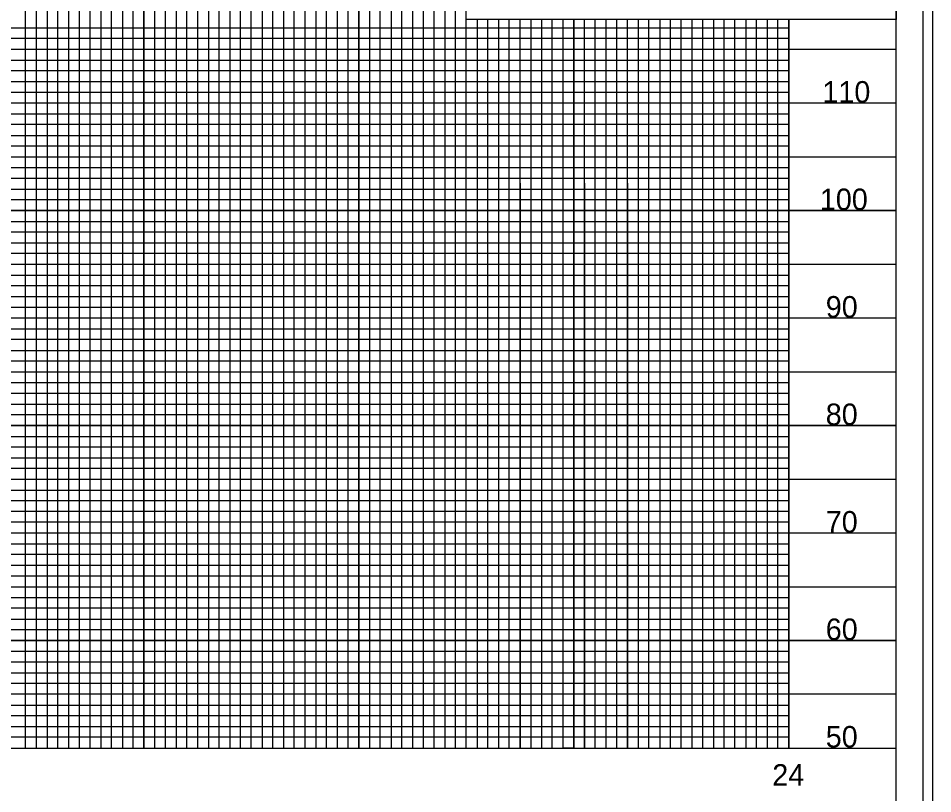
# Model space of a CAD drawing. Extents: x 2367101 to 2368930, y 803279 to 808979.
# Drawn here: x 2368359.6 to 2368785, y 803832.7 to 804193.5 of the extents above; entities that cross this region are included whole.
import ezdxf

# ---------------------------------------------------------------- set-up
doc = ezdxf.new("R2010")
doc.units = 0
for name, color, linetype in [('Old_Level_11', 7, 'Continuous'), ('Old_Level_12', 7, 'Continuous'), ('Old_Level_13', 7, 'Continuous'), ('Old_Level_17', 7, 'Continuous'), ('Old_Level_19', 7, 'Continuous'), ('Old_Level_4', 7, 'Continuous'), ('Old_Level_6', 7, 'Continuous'), ('Old_Level_63', 7, 'Continuous'), ('Old_Level_8', 7, 'Continuous'), ('Old_Level_9', 7, 'Continuous'), ('Plan Sheet CELL', 7, 'Continuous')]:
    doc.layers.add(name, color=color, linetype=linetype)

msp = doc.modelspace()

# ---------------------------------------------------------------- linework, layer by layer
at = {"layer": 'Old_Level_11'}
for points in [[(2368317.97, 803853.98), (2368367.97, 803853.98), (2368367.97, 804353.98), (2368417.97, 804353.98), (2368417.97, 803853.98), (2368467.97, 803853.98), (2368467.97, 804353.98), (2368517.97, 804353.98), (2368517.97, 803853.98), (2368567.97, 803853.98), (2368567.97, 804353.98), (2368594.27, 804353.98)], [(2368717.97, 804192.93), (2368717.97, 803853.98), (2368767.97, 803853.98), (2368767.97, 804203.98)], [(2368617.97, 804192.93), (2368617.97, 803853.98), (2368667.97, 803853.98), (2368667.97, 803853.98), (2368667.97, 804192.93)], [(2368767.97, 804153.98), (2367267.97, 804153.98), (2367267.97, 804103.98), (2368767.97, 804103.98)], [(2368767.97, 804053.98), (2367267.97, 804053.98), (2367267.97, 804003.98), (2368767.97, 804003.98)], [(2368767.97, 803953.98), (2367267.97, 803953.98), (2367267.97, 803953.98), (2367267.97, 803903.98), (2368767.97, 803903.98)]]:
    msp.add_lwpolyline(points, dxfattribs=at)
at = {"layer": 'Old_Level_12'}
for points in [[(2368342.97, 803853.98), (2368392.97, 803853.98), (2368392.97, 804353.98), (2368442.97, 804353.98), (2368442.97, 803853.98), (2368492.97, 803853.98), (2368492.97, 804353.98), (2368542.97, 804353.98), (2368542.97, 803853.98), (2368592.97, 803853.98), (2368592.97, 804192.93)], [(2368592.97, 804116.78), (2368592.97, 803853.98), (2368642.97, 803853.98), (2368642.97, 804192.93)], [(2368642.97, 804116.78), (2368642.97, 803853.98), (2368692.97, 803853.98), (2368692.97, 804192.93)], [(2368767.97, 804178.98), (2367267.97, 804178.98), (2367267.97, 804128.98), (2368592.97, 804128.98)], [(2368592.97, 804128.98), (2368767.97, 804128.98)], [(2368767.97, 804078.98), (2367267.97, 804078.98), (2367267.97, 804028.98), (2368767.97, 804028.98)], [(2368767.97, 803978.98), (2367267.97, 803978.98), (2367267.97, 803928.98), (2368767.97, 803928.98)], [(2368767.97, 803878.98), (2367267.97, 803878.98)]]:
    msp.add_lwpolyline(points, dxfattribs=at)
at = {"layer": 'Old_Level_13'}
for p, q in [((2368367.97, 803853.98), (2368367.97, 804353.98)), ((2368417.97, 803853.98), (2368417.97, 804353.98)), ((2368467.97, 803853.98), (2368467.97, 804353.98)), ((2368517.97, 803853.98), (2368517.97, 804353.98)), ((2368567.97, 803853.98), (2368567.97, 804216.43)), ((2368617.97, 803853.98), (2368617.97, 804192.93)), ((2368667.97, 803853.98), (2368667.97, 804192.93)), ((2368717.97, 803853.98), (2368717.97, 804192.93)), ((2368767.97, 804153.98), (2367267.97, 804153.98)), ((2368767.97, 804103.98), (2367267.97, 804103.98)), ((2368767.97, 804053.98), (2367267.97, 804053.98)), ((2368767.97, 804003.98), (2367267.97, 804003.98)), ((2368767.97, 803953.98), (2367267.97, 803953.98)), ((2368767.97, 803903.98), (2367267.97, 803903.98))]:
    msp.add_line(p, q, dxfattribs=at)
at = {"layer": 'Old_Level_4'}
msp.add_lwpolyline([(2367113.97, 803301.43), (2368780.47, 803301.43), (2368780.47, 804356.53), (2367113.97, 804356.53)], close=True, dxfattribs=at)
at = {"layer": 'Old_Level_6'}
msp.add_lwpolyline([(2367100.97, 803278.98), (2368784.97, 803278.98), (2368784.97, 804378.98), (2367100.97, 804378.98)], close=True, dxfattribs=at)
at = {"layer": 'Old_Level_63'}
msp.add_lwpolyline([(2367317.97, 804192.93), (2367317.97, 803853.98), (2368717.97, 803853.98), (2368717.97, 804192.93)], dxfattribs=at)
at = {"layer": 'Old_Level_8'}
for p, q in [((2367317.97, 804188.98), (2368717.97, 804188.98)), ((2368717.97, 804168.98), (2367317.97, 804168.98)), ((2367317.97, 804163.98), (2368717.97, 804163.98)), ((2368717.97, 804143.98), (2367317.97, 804143.98)), ((2367317.97, 804138.98), (2368717.97, 804138.98)), ((2368717.97, 804118.98), (2367317.97, 804118.98)), ((2367317.97, 804113.98), (2368717.97, 804113.98)), ((2368717.97, 804108.98), (2367317.97, 804108.98)), ((2367317.97, 804098.98), (2368717.97, 804098.98)), ((2368717.97, 804093.98), (2367317.97, 804093.98)), ((2367317.97, 804088.98), (2368717.97, 804088.98)), ((2368717.97, 804083.98), (2367317.97, 804083.98)), ((2367317.97, 804073.98), (2368717.97, 804073.98)), ((2368717.97, 804068.98), (2367317.97, 804068.98)), ((2367317.97, 804063.98), (2368717.97, 804063.98)), ((2368717.97, 804058.98), (2367317.97, 804058.98)), ((2367317.97, 804048.98), (2368717.97, 804048.98)), ((2368717.97, 804043.98), (2367317.97, 804043.98)), ((2367317.97, 804038.98), (2368717.97, 804038.98)), ((2368717.97, 804033.98), (2367317.97, 804033.98)), ((2367317.97, 804023.98), (2368717.97, 804023.98)), ((2368717.97, 804018.98), (2367317.97, 804018.98)), ((2367317.97, 804013.98), (2368717.97, 804013.98)), ((2368717.97, 804008.98), (2367317.97, 804008.98)), ((2367317.97, 803998.98), (2368717.97, 803998.98)), ((2368717.97, 803993.98), (2367317.97, 803993.98)), ((2367317.97, 803988.98), (2368717.97, 803988.98)), ((2368717.97, 803983.98), (2367317.97, 803983.98)), ((2367317.97, 803973.98), (2368717.97, 803973.98)), ((2368717.97, 803968.98), (2367317.97, 803968.98)), ((2368717.97, 803963.98), (2367317.97, 803963.98)), ((2368717.97, 803958.98), (2367317.97, 803958.98)), ((2367317.97, 803948.98), (2368717.97, 803948.98)), ((2368717.97, 803943.98), (2367317.97, 803943.98)), ((2367317.97, 803938.98), (2368717.97, 803938.98)), ((2368717.97, 803933.98), (2367317.97, 803933.98)), ((2367317.97, 803923.98), (2368717.97, 803923.98)), ((2368717.97, 803918.98), (2367317.97, 803918.98)), ((2367317.97, 803913.98), (2368717.97, 803913.98)), ((2368717.97, 803908.98), (2367317.97, 803908.98)), ((2367317.97, 803898.98), (2368717.97, 803898.98)), ((2368717.97, 803893.98), (2367317.97, 803893.98)), ((2367317.97, 803888.98), (2368717.97, 803888.98)), ((2368717.97, 803883.98), (2367317.97, 803883.98)), ((2367317.97, 803873.98), (2368717.97, 803873.98)), ((2368717.97, 803868.98), (2367317.97, 803868.98)), ((2367317.97, 803863.98), (2368717.97, 803863.98))]:
    msp.add_line(p, q, dxfattribs=at)
for points in [[(2368357.97, 803853.98), (2368362.97, 803853.98), (2368362.97, 804353.98)], [(2368372.97, 804353.98), (2368372.97, 803853.98), (2368377.97, 803853.98), (2368377.97, 804353.98)], [(2368382.97, 804353.98), (2368382.97, 803853.98), (2368387.97, 803853.98), (2368387.97, 804353.98)], [(2368397.97, 804353.98), (2368397.97, 803853.98), (2368402.97, 803853.98), (2368402.97, 804353.98)], [(2368407.97, 804353.98), (2368407.97, 803853.98), (2368412.97, 803853.98), (2368412.97, 804353.98)], [(2368422.97, 804353.98), (2368422.97, 803853.98), (2368427.97, 803853.98), (2368427.97, 804353.98)], [(2368432.97, 804353.98), (2368432.97, 803853.98), (2368437.97, 803853.98), (2368437.97, 804353.98)], [(2368447.97, 804353.98), (2368447.97, 803853.98), (2368452.97, 803853.98), (2368452.97, 804353.98)], [(2368457.97, 804353.98), (2368457.97, 803853.98)], [(2368457.97, 803853.98), (2368462.97, 803853.98), (2368462.97, 804353.98)], [(2368472.97, 804353.98), (2368472.97, 803853.98), (2368477.97, 803853.98), (2368477.97, 804353.98)], [(2368482.97, 804353.98), (2368482.97, 803853.98), (2368487.97, 803853.98), (2368487.97, 804353.98)], [(2368497.97, 804353.98), (2368497.97, 803853.98), (2368502.97, 803853.98), (2368502.97, 804353.98)], [(2368507.97, 804353.98), (2368507.97, 803853.98), (2368512.97, 803853.98), (2368512.97, 804353.98)], [(2368522.97, 804353.98), (2368522.97, 803853.98), (2368527.97, 803853.98), (2368527.97, 804353.98)], [(2368532.97, 804353.98), (2368532.97, 803853.98), (2368537.97, 803853.98), (2368537.97, 804353.98)], [(2368547.97, 804353.98), (2368547.97, 803853.98), (2368552.97, 803853.98), (2368552.97, 804353.98)], [(2368557.97, 804353.98), (2368557.97, 803853.98), (2368562.97, 803853.98), (2368562.97, 804353.98)], [(2368572.97, 804192.93), (2368572.97, 803853.98), (2368577.97, 803853.98), (2368577.97, 804192.93)], [(2368582.97, 804192.93), (2368582.97, 803853.98), (2368587.97, 803853.98), (2368587.97, 804192.93)], [(2368597.97, 804192.93), (2368597.97, 803853.98), (2368597.97, 803853.98), (2368602.97, 803853.98), (2368607.97, 803853.98), (2368607.97, 804192.93)], [(2368602.97, 804192.93), (2368602.97, 803853.98)], [(2368612.97, 804192.93), (2368612.87, 803854.03), (2368617.87, 803854.03), (2368622.97, 803853.98), (2368622.97, 804192.93)], [(2368622.97, 804116.78), (2368622.97, 803853.98), (2368627.97, 803853.98), (2368627.97, 804192.93)], [(2368632.97, 804192.93), (2368632.97, 803853.98), (2368637.97, 803853.98), (2368637.97, 804192.93)], [(2368647.97, 804192.93), (2368647.97, 803853.98), (2368652.97, 803853.98), (2368652.97, 804192.93)], [(2368657.97, 804192.93), (2368657.97, 803853.98), (2368662.97, 803853.98), (2368662.97, 804192.93)], [(2368672.97, 804192.93), (2368672.97, 803853.98), (2368677.97, 803853.98), (2368677.97, 804192.93)], [(2368682.97, 804192.93), (2368682.97, 803853.98), (2368687.97, 803853.98), (2368687.97, 804192.93)], [(2368697.97, 804192.93), (2368697.97, 803853.98), (2368702.97, 803853.98), (2368702.97, 804192.93)], [(2368707.97, 804192.93), (2368707.97, 803853.98), (2368712.97, 803853.98), (2368712.97, 804192.93)], [(2368717.97, 804183.98), (2367317.97, 804183.98), (2367317.97, 804173.98), (2368717.97, 804173.98)], [(2368717.97, 804158.98), (2367317.97, 804158.98), (2367317.97, 804148.98), (2368717.97, 804148.98)], [(2368717.97, 804133.98), (2367317.97, 804133.98), (2367317.97, 804123.98), (2368717.97, 804123.98)], [(2368717.97, 803858.98), (2367317.97, 803858.98)]]:
    msp.add_lwpolyline(points, dxfattribs=at)
at = {"layer": 'Old_Level_9'}
msp.add_line((2367267.97, 803853.98), (2368767.97, 803853.98), dxfattribs=at)
msp.add_lwpolyline([(2368767.97, 804353.98), (2367267.97, 804353.98), (2367267.97, 803303.98), (2368767.97, 803303.98)], close=True, dxfattribs=at)
at = {"layer": 'Plan Sheet CELL'}
for p, q in [((2368567.92, 804192.93), (2368567.92, 804216.43)), ((2368567.92, 804192.93), (2368567.92, 804216.43)), ((2368767.96, 804216.42), (2368767.96, 804192.92)), ((2368767.96, 804216.42), (2368767.96, 804192.92)), ((2368767.96, 804192.93), (2368567.92, 804192.93)), ((2368767.96, 804192.93), (2368567.92, 804192.93))]:
    msp.add_line(p, q, dxfattribs=at)

# ---------------------------------------------------------------- texts
at = {"layer": 'Old_Level_17'}
for s, p in [('110', (2368733.65, 804154.23)), ('100', (2368732.46, 804104.23)), ('90', (2368735.21, 804054.23)), ('80', (2368735.21, 804004.23)), ('70', (2368735.21, 803954.23)), ('60', (2368735.21, 803904.23)), ('50', (2368735.21, 803854.23))]:
    msp.add_text(s, height=10, dxfattribs=at).set_placement(p)
at = {"layer": 'Old_Level_19'}
msp.add_text('24', height=10, dxfattribs=at).set_placement((2368710.34, 803836.48))

doc.saveas('drawing.dxf')
